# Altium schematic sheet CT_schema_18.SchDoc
size 145 x 119 mm
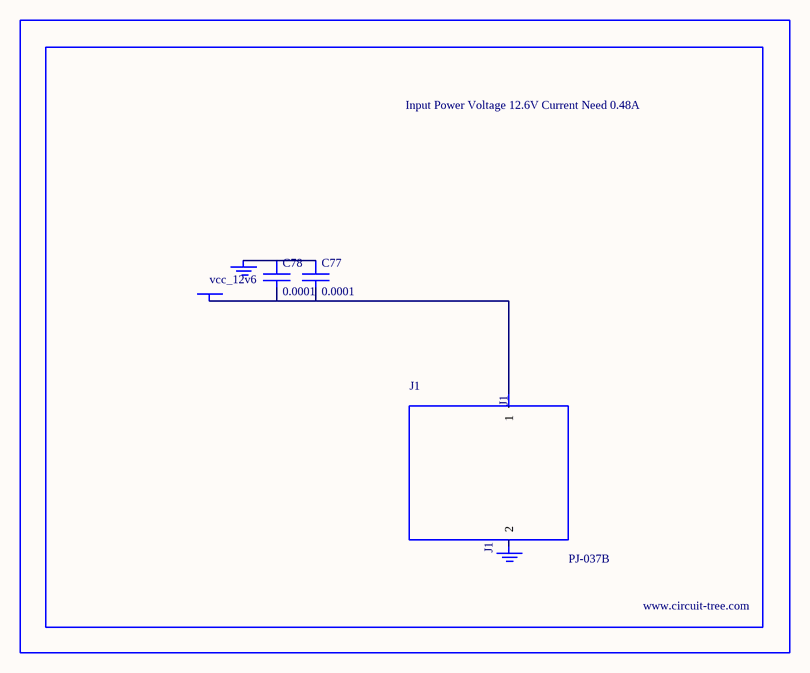
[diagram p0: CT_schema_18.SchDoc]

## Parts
BORDER17  (no value)
C77  0.0001  [EXV-9H]
C78  0.0001  [EXV-9H]
GND_INSTANCE_17_0  (no value)
GND_INSTANCE_17_1  (no value)
J1  PJ-037B  [PJ-037B_PACKAGE]
POWER_INSTANCE_17_0  vcc_12v6

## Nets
NetC77_1: C77.1 C78.1 GND_INSTANCE_17_0.0(GND)
NetC77_2: C77.2 C78.2 J1.1 POWER_INSTANCE_17_0.0(PWR)

Not connected (* = marked no-connect by the designer): GND_INSTANCE_17_1 0(GND); J1 2

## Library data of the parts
BORDER17 = BORDER_PAGE17
C77 C78 = EDK107M035A9HAA
GND_INSTANCE_17_0 GND_INSTANCE_17_1 = GND
POWER_INSTANCE_17_0 = PWR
